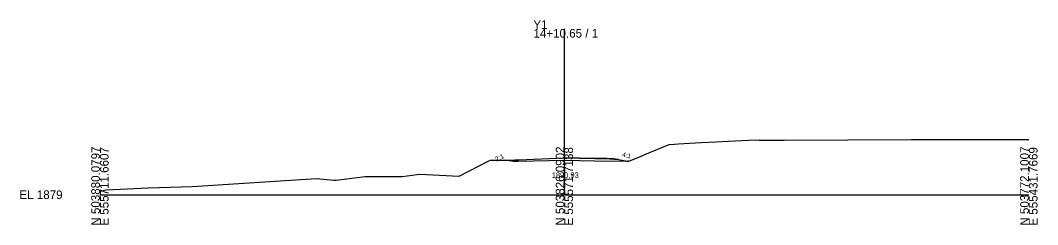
# Model space of a CAD drawing. Extents: x -26 to 1503, y -10 to 5015.
# Drawn here: x 1174.3 to 1502.8, y 490.3 to 556.4 of the extents above; entities that cross this region are included whole.
import ezdxf

# ---------------------------------------------------------------- set-up
doc = ezdxf.new("R2010")
doc.units = 0
for name, color, linetype in [('Exist Cross Section Cell', 7, 'Continuous'), ('Exist XS Ground Line', 7, 'Continuous'), ('Prop CMT Pvmt Surface Shoulder', 7, 'Continuous'), ('Prop CMT Shld Paved Course 1', 7, 'Continuous'), ('Prop XS Ditch Standard Text', 7, 'Continuous'), ('Prop XS Earthwork Shape', 7, 'Continuous'), ('Prop XS Side Slope Text', 7, 'Continuous')]:
    doc.layers.add(name, color=color, linetype=linetype)

msp = doc.modelspace()

# ---------------------------------------------------------------- linework, layer by layer
at = {"layer": 'Exist Cross Section Cell'}
for p, q in [((1350, 500), (1350, 553.64)), ((1200, 500), (1350, 500)), ((1350, 500), (1500, 500))]:
    msp.add_line(p, q, dxfattribs=at)
at = {"layer": 'Exist XS Ground Line'}
msp.add_lwpolyline([(1200, 501.18), (1202.01, 501.63), (1215.62, 502.28), (1229.79, 502.63), (1269.97, 505.22), (1275.55, 504.7), (1276.35, 504.7), (1285.63, 505.85), (1293.19, 505.87), (1297.65, 505.95), (1302.45, 506.51), (1303.16, 506.64), (1305.49, 506.53), (1315.98, 506.06), (1325.65, 510.94), (1326.13, 511.18), (1332.4, 511.24), (1334.05, 511.28), (1335.25, 511.33), (1350, 511.93), (1350.56, 511.95), (1363.68, 511.78), (1365.95, 511.75), (1370.64, 510.77), (1372.14, 511.38), (1374.03, 512.13), (1375.98, 512.98), (1383.82, 516.22), (1385.54, 516.35), (1386.88, 516.46), (1394.17, 516.86), (1398.97, 517.12), (1402.99, 517.32), (1411.64, 517.74), (1412.9, 517.7), (1421.01, 517.68), (1462.1, 517.86), (1468.35, 517.88), (1473.14, 517.87), (1500, 517.82)], dxfattribs=at)
at = {"layer": 'Prop CMT Pvmt Surface Shoulder'}
msp.add_lwpolyline([(1365, 511.64), (1365, 511.64)], dxfattribs=at)
at = {"layer": 'Prop CMT Shld Paved Course 1'}
msp.add_lwpolyline([(1365, 511.64), (1365, 511.64)], dxfattribs=at)
at = {"layer": 'Prop XS Earthwork Shape'}
for points in [[(1332.4, 511.24), (1334.05, 511.28), (1335.25, 511.33), (1350, 511.94), (1364.72, 511.64), (1367.53, 511.42), (1370.43, 510.81), (1364.72, 510.77), (1350, 511.06), (1335, 510.76), (1333.61, 510.73), (1330.82, 511.23)], [(1350.56, 511.95), (1363.68, 511.78), (1365.95, 511.75), (1367.53, 511.42), (1364.72, 511.64), (1350, 511.94)], [(1370.64, 510.77), (1370.76, 510.81), (1370.43, 510.81)]]:
    msp.add_lwpolyline(points, close=True, dxfattribs=at)

# ---------------------------------------------------------------- texts
at = {"layer": 'Exist Cross Section Cell'}
for s, p in [('Y1', (1340, 553.64)), ('14+10.65 / 1', (1340, 550.84)), ('EL 1879', (1174, 498.6))]:
    msp.add_text(s, height=2.8, dxfattribs=at).set_placement(p)
for s, p in [('N 503880.0797', (1200, 490)), ('E 555711.6607', (1202.8, 490)), ('N 503826.0902', (1350, 490)), ('E 555571.7138', (1352.8, 490)), ('N 503772.1007', (1500, 490)), ('E 555431.7669', (1502.8, 490))]:
    msp.add_text(s, height=2.8, rotation=90, dxfattribs=at).set_placement(p)
at = {"layer": 'Prop XS Ditch Standard Text'}
msp.add_text('1890.93', height=1.8, dxfattribs=at).set_placement((1345.93, 505.45))
at = {"layer": 'Prop XS Side Slope Text'}
for s, rotation, p in [('2:1', 26.5651, (1328.11, 510.71)), ('2:1', 26.5651, (1328.11, 510.71)), ('4:1', 345.9638, (1368.54, 512.4))]:
    msp.add_text(s, height=1.5, rotation=rotation, dxfattribs=at).set_placement(p)

doc.saveas('drawing.dxf')
